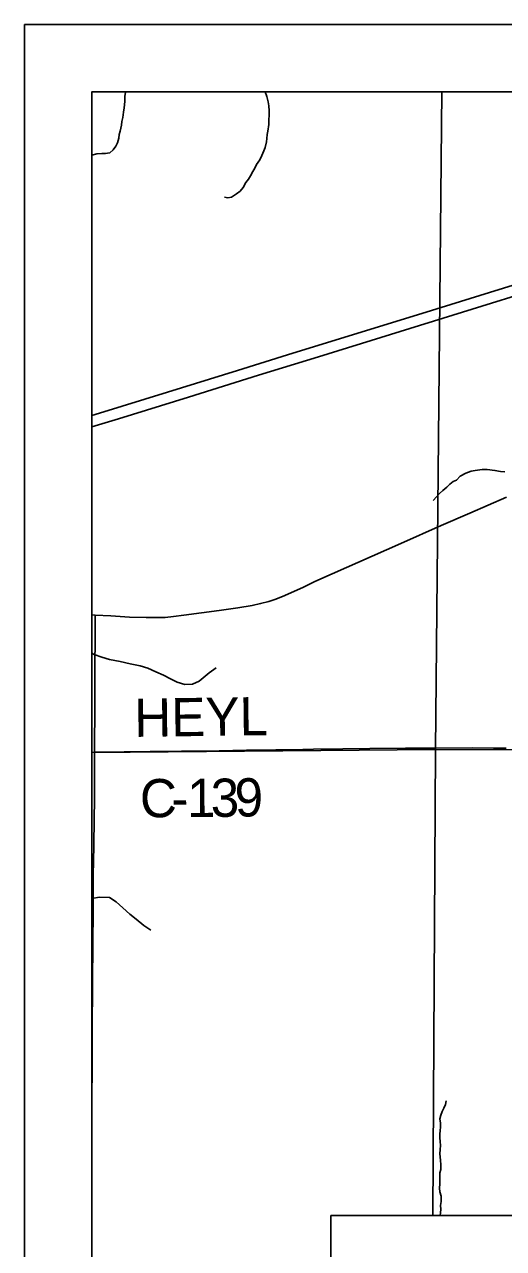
# Model space of a CAD drawing. Extents: x 0 to 34, y 0 to 22.
# Drawn here: x 2 to 2.711, y 19.182 to 21 of the extents above; entities that cross this region are included whole.
import ezdxf

# ---------------------------------------------------------------- set-up
doc = ezdxf.new("R2010")
doc.units = 0
for name, color, linetype in [('Default', 7, 'Continuous'), ('GM_X_County_Road', 7, 'Continuous'), ('GM_X_County_Road_Text', 7, 'Continuous'), ('GM_X_Minor_River', 7, 'Continuous'), ('GM_X_Section', 7, 'Continuous'), ('GM_X_State_Route', 7, 'Continuous'), ('GM_X_US_Route', 7, 'Continuous'), ('SH_Data', 7, 'Continuous'), ('SH_Text', 7, 'Continuous')]:
    doc.layers.add(name, color=color, linetype=linetype)

msp = doc.modelspace()

# ---------------------------------------------------------------- linework, layer by layer
at = {"layer": 'Default'}
for points in [[(2.6196, 20.9), (2.1, 20.9), (2.1, 19.9187), (2.6102, 19.9231)], [(3.6554, 20.9), (2.6196, 20.9), (2.6102, 19.9231), (3.6434, 19.919)], [(2.6062, 19.2311), (2.6102, 19.9231), (2.1, 19.9187), (2.1, 18.9091), (2.4548, 18.9153), (2.4548, 19.2311)]]:
    msp.add_lwpolyline(points, close=True, dxfattribs=at)
at = {"layer": 'GM_X_County_Road'}
msp.add_line((2.1, 20.1232), (2.1049, 20.1229), dxfattribs=at)
for points in [[(2.1049, 20.1229), (2.128, 20.1215), (2.1559, 20.1199), (2.1807, 20.1192), (2.1962, 20.1191), (2.2087, 20.1195), (2.2212, 20.1206), (2.2365, 20.1225), (2.2889, 20.1298), (2.3166, 20.1337), (2.3382, 20.1372), (2.3504, 20.1398), (2.3625, 20.1431), (2.3714, 20.146), (2.383, 20.1504), (2.3999, 20.1578), (2.4142, 20.1645), (2.431, 20.1725), (2.4565, 20.1841), (2.5162, 20.2103), (2.5588, 20.2292), (2.6185, 20.2557), (2.6611, 20.274), (2.7153, 20.298)], [(2.1039, 19.9194), (2.1038, 19.9339), (2.1042, 19.9772), (2.1044, 19.999), (2.1045, 20.0394), (2.1045, 20.0612), (2.1047, 20.0736), (2.1049, 20.1078), (2.1049, 20.1152), (2.1049, 20.1208), (2.1049, 20.1229)], [(2.1039, 19.9194), (2.1088, 19.9195), (2.1865, 19.9203), (2.2331, 19.9209), (2.2891, 19.9214), (2.3295, 19.9221), (2.373, 19.9227), (2.4134, 19.9233), (2.4289, 19.9237), (2.4724, 19.9242), (2.5128, 19.9246), (2.5657, 19.925), (2.6092, 19.9253), (2.6651, 19.9255), (2.6962, 19.9254), (2.7149, 19.9253)], [(2.1, 19.394), (2.1001, 19.4091), (2.1005, 19.4464), (2.1004, 19.4743), (2.1005, 19.5083), (2.1006, 19.53), (2.1008, 19.5512), (2.1011, 19.5892), (2.1013, 19.6232), (2.1014, 19.6382), (2.1015, 19.6508), (2.1018, 19.6667), (2.1018, 19.704), (2.1019, 19.7165), (2.1021, 19.7375), (2.1023, 19.7566), (2.1027, 19.7817), (2.1032, 19.8189), (2.1037, 19.85), (2.104, 19.8717), (2.104, 19.9059), (2.1039, 19.9194)]]:
    msp.add_lwpolyline(points, dxfattribs=at)
at = {"layer": 'GM_X_Minor_River'}
for points in [[(2.1504, 20.9), (2.1501, 20.8993), (2.149, 20.8929), (2.149, 20.8856), (2.1479, 20.8761), (2.1468, 20.8697), (2.1461, 20.8617), (2.1446, 20.856), (2.1439, 20.8503), (2.142, 20.8415), (2.1405, 20.8366), (2.1398, 20.8309), (2.138, 20.8244), (2.1357, 20.8191), (2.1316, 20.8137), (2.1266, 20.8095), (2.1198, 20.8083), (2.1149, 20.8083), (2.1073, 20.8079), (2.1001, 20.806), (2.1, 20.8059)], [(2.3574, 20.9), (2.3596, 20.8931), (2.3616, 20.8851), (2.3627, 20.879), (2.3631, 20.8718), (2.3632, 20.8646), (2.3628, 20.8589), (2.3625, 20.8516), (2.361, 20.8417), (2.3603, 20.8364), (2.3599, 20.8307), (2.3592, 20.8258), (2.3574, 20.8174), (2.3551, 20.8121), (2.3521, 20.8052), (2.3495, 20.7991), (2.3446, 20.7919), (2.342, 20.7865), (2.3389, 20.7816), (2.3356, 20.7751), (2.3326, 20.7701), (2.3288, 20.7652), (2.3247, 20.7579), (2.3201, 20.7526), (2.3148, 20.7484), (2.3073, 20.7434), (2.302, 20.7426), (2.297, 20.7434)], [(2.7132, 20.3358), (2.7064, 20.3361), (2.6984, 20.3376), (2.687, 20.3391), (2.6794, 20.339), (2.6692, 20.3375), (2.6631, 20.3367), (2.6552, 20.3336), (2.6468, 20.329), (2.6412, 20.3233), (2.6363, 20.321), (2.6313, 20.3175), (2.6268, 20.3126), (2.6208, 20.308)], [(2.6208, 20.308), (2.6159, 20.3034), (2.6068, 20.2931)], [(2.1, 20.0664), (2.1036, 20.0643), (2.1146, 20.0602), (2.126, 20.0569), (2.1419, 20.0539), (2.1571, 20.0506), (2.1719, 20.0477), (2.1833, 20.0439), (2.195, 20.0387), (2.2061, 20.0338), (2.2167, 20.0282), (2.2266, 20.023), (2.2379, 20.0196), (2.2493, 20.0201), (2.2595, 20.0247), (2.2742, 20.0369), (2.2844, 20.0445)], [(2.1, 19.7021), (2.1113, 19.7037), (2.1264, 19.7034), (2.1363, 19.697), (2.1462, 19.688), (2.1565, 19.6789), (2.166, 19.671), (2.1774, 19.6616), (2.1877, 19.6548)], [(2.616, 19.2719), (2.6163, 19.278), (2.6167, 19.2863), (2.6166, 19.2943), (2.6181, 19.2996), (2.6181, 19.3069), (2.6173, 19.3129), (2.6165, 19.3232), (2.6172, 19.3289), (2.6175, 19.3358), (2.6171, 19.3407), (2.6167, 19.3468), (2.6167, 19.3521), (2.617, 19.3574), (2.6174, 19.3624), (2.6174, 19.3681), (2.6166, 19.3749), (2.6181, 19.3802), (2.6199, 19.3856), (2.6226, 19.3905), (2.6248, 19.3959), (2.6259, 19.4012)], [(2.6169, 19.2311), (2.6177, 19.235), (2.618, 19.2407), (2.6176, 19.246), (2.6183, 19.2521), (2.6183, 19.2597), (2.6164, 19.2662), (2.616, 19.2719)]]:
    msp.add_lwpolyline(points, dxfattribs=at)
at = {"layer": 'GM_X_Section'}
msp.add_lwpolyline([(3.6346, 19.2311), (3.6434, 19.919), (2.6102, 19.9231), (2.6062, 19.2311)], close=True, dxfattribs=at)
at = {"layer": 'GM_X_State_Route'}
msp.add_lwpolyline([(5.6507, 20.9), (2.1, 20.9), (2.1, 15.8695)], dxfattribs=at)
at = {"layer": 'GM_X_US_Route'}
for points in [[(2.1, 20.4023), (2.1394, 20.4145), (2.2433, 20.4467), (2.3472, 20.4789), (2.4363, 20.5065), (2.9854, 20.6765), (3.2616, 20.7618), (3.3387, 20.7859), (3.4248, 20.8127), (3.4843, 20.8307), (3.5142, 20.8391), (3.5413, 20.8461), (3.5656, 20.8516), (3.59, 20.8565), (3.6175, 20.8614), (3.6452, 20.8655), (3.673, 20.869), (3.7009, 20.8717), (3.7288, 20.8736), (3.7537, 20.8748), (3.7847, 20.8756), (3.8531, 20.8766), (3.9805, 20.8784)], [(2.1, 20.4192), (2.1112, 20.4227), (2.2121, 20.454), (2.3162, 20.4859), (2.3903, 20.5091), (2.6041, 20.5753), (2.797, 20.6352)]]:
    msp.add_lwpolyline(points, dxfattribs=at)
at = {"layer": 'SH_Data'}
for p, q in [((2, 21), (9, 21)), ((2, 21), (2, 14)), ((2.1, 20.9), (2.1, 14.1)), ((2.1, 20.9), (8.9, 20.9))]:
    msp.add_line(p, q, dxfattribs=at)
at = {"layer": 'SH_Text'}
msp.add_lwpolyline([(2.4548, 19.2311), (4.6746, 19.2311), (4.6746, 18.514), (2.4548, 18.514)], close=True, dxfattribs=at)

# ---------------------------------------------------------------- texts
at = {"layer": 'GM_X_County_Road_Text'}
for s, height, rotation, p in [('HEYL', 0.05682, 0.7631, (2.1633, 19.9419)), ('C', 0.0568, 0.3025, (2.1715, 19.8224)), ('1', 0.0568, 0.353, (2.2415, 19.8228)), ('3', 0.0568, 0.5015, (2.2767, 19.823)), ('9', 0.0568, 1.3059, (2.3126, 19.8233)), ('-', 0.0568, 0.3158, (2.2182, 19.8226))]:
    msp.add_text(s, height=height, rotation=rotation, dxfattribs=at).set_placement(p)

doc.saveas('drawing.dxf')
